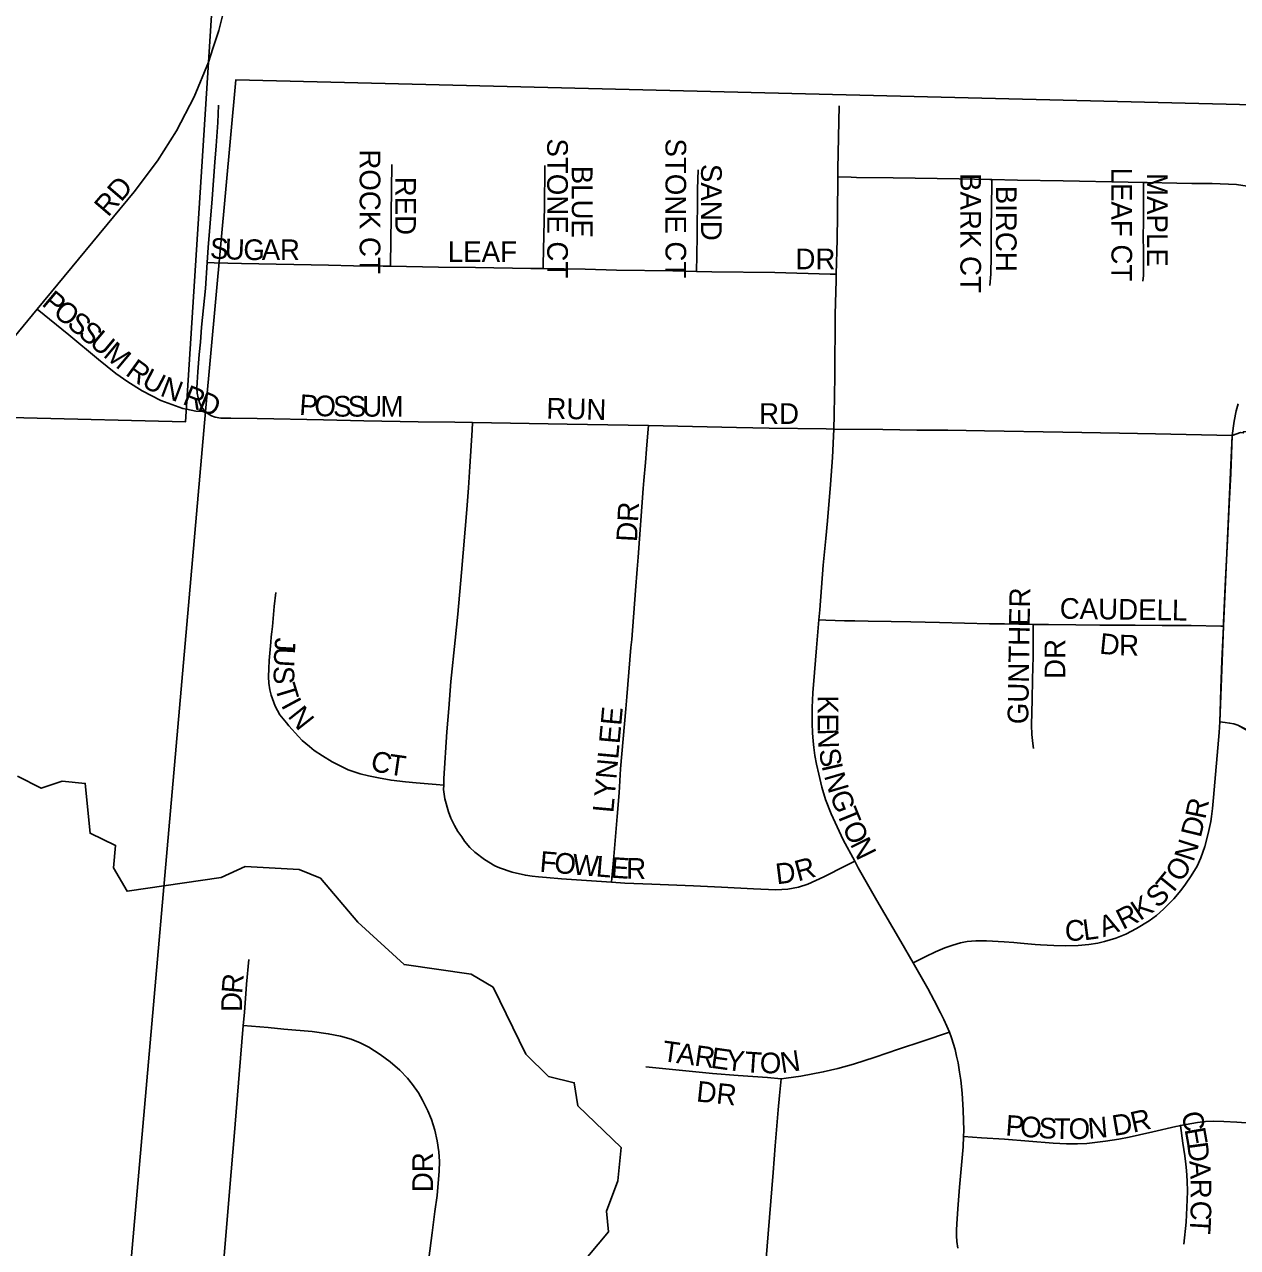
# Model space of a CAD drawing. Extents: x 1410790 to 1770854, y 448063 to 770588.
# Drawn here: x 1517804 to 1520737, y 603957 to 606914 of the extents above; entities that cross this region are included whole.
import ezdxf

# ---------------------------------------------------------------- set-up
doc = ezdxf.new("R2010")
doc.units = 0
for name, color, linetype in [('GM_X_City_Street', 7, 'Continuous'), ('GM_X_City_Street_Text', 7, 'Continuous'), ('GM_X_Corporation', 7, 'Continuous'), ('GM_X_Minor_River', 7, 'Continuous'), ('GM_X_Township_Road', 7, 'Continuous')]:
    doc.layers.add(name, color=color, linetype=linetype)

msp = doc.modelspace()

# ---------------------------------------------------------------- linework, layer by layer
at = {"layer": 'GM_X_City_Street'}
for points in [[(1517616.1, 605962), (1517834.7, 606226.3), (1518069.3, 606510), (1518125.8, 606584.8), (1518171.8, 606657.6), (1518214.2, 606739.2), (1518249, 606822.9), (1518259.8, 606856)], [(1519770.4, 606545.8), (1519770.5, 606565), (1519773.9, 606717.3)], [(1518688.6, 606329.9), (1518688.8, 606341), (1518689.8, 606384), (1518690.8, 606456.1), (1518692.1, 606575.6)], [(1519058.1, 606324.3), (1519058.3, 606334.2), (1519061, 606475.4), (1519062, 606567.3), (1519062.2, 606573.8)], [(1519428.7, 606317.5), (1519429.4, 606355.4), (1519430.3, 606404.3), (1519431.2, 606504.1), (1519431.3, 606516.4), (1519432.5, 606562.7)], [(1519766.4, 606310.4), (1519766.4, 606310.4), (1519768.5, 606394.3), (1519769.6, 606453.4), (1519770.4, 606545.8)], [(1520142.9, 606539.8), (1520137.7, 606539.9), (1520064, 606540.9), (1519903.9, 606543.3), (1519815.7, 606544.5), (1519802.7, 606544.8), (1519770.4, 606545.8)], [(1520138, 606283.5), (1520140.3, 606310.9), (1520141.3, 606355.2), (1520141.3, 606417.4), (1520142.8, 606531), (1520142.9, 606539.8)], [(1520509.3, 606532.5), (1520472.5, 606533.5), (1520315.4, 606536.7), (1520204.3, 606537.8), (1520142.9, 606539.8)], [(1520508, 606293.7), (1520509.3, 606307.1), (1520509.3, 606319.8), (1520509.3, 606342.7), (1520508.9, 606364.3), (1520508.8, 606403.2), (1520509.2, 606435.8), (1520509.3, 606522.1), (1520509.3, 606532.5)], [(1520759.8, 606523.6), (1520733.9, 606527.1), (1520675.2, 606529.5), (1520626.1, 606529.8), (1520590.2, 606530.6), (1520518.3, 606532.3), (1520509.3, 606532.5)], [(1518246, 606338.6), (1518262.8, 606338.1), (1518329.1, 606336.2), (1518538.8, 606332.8), (1518599.6, 606331.1), (1518671.4, 606330.3), (1518688.6, 606329.9)], [(1518688.6, 606329.9), (1518804.8, 606327.4), (1518894.1, 606326.4), (1519028.5, 606324.7), (1519058.1, 606324.3)], [(1519058.1, 606324.3), (1519159.6, 606323), (1519235, 606320.5), (1519371.2, 606318.6), (1519428.7, 606317.5)], [(1519428.7, 606317.5), (1519465.8, 606316.7), (1519618.4, 606314.4), (1519751.5, 606310.8), (1519766.4, 606310.4)], [(1519760.6, 605936.3), (1519761.3, 605970.2), (1519763.3, 606064.1), (1519764.1, 606213.6), (1519766, 606295.7), (1519766.4, 606310.4)], [(1517834.7, 606226.3), (1517911.4, 606164.2), (1517983.4, 606104.5), (1518024.8, 606070.3), (1518053.9, 606050.7), (1518088.8, 606028.2), (1518133.9, 606005.6), (1518187, 605986), (1518195.7, 605984.3)], [(1518241.8, 605978.4), (1518248.2, 605972.7), (1518256.1, 605968.1), (1518265.2, 605964.9), (1518278.8, 605962.8), (1518302.9, 605962.6), (1518366.5, 605961.4), (1518526.7, 605958.4), (1518624.8, 605956.3), (1518755.9, 605953.6), (1518844.3, 605952.7), (1518887.3, 605951.9)], [(1520723.6, 605920.9), (1520728.5, 605955.6), (1520733.3, 605980.2), (1520737.8, 605997.2)], [(1518817.8, 605075.5), (1518818.2, 605090.9), (1518825.1, 605203.8), (1518829.6, 605260.8), (1518835.2, 605326.2), (1518845, 605425.5), (1518851.7, 605488.5), (1518860.4, 605589.5), (1518873.5, 605741.8), (1518877.2, 605793.8), (1518880.6, 605845.4), (1518886.1, 605933.5), (1518887.3, 605951.9)], [(1518887.3, 605951.9), (1519116, 605947.9), (1519263.4, 605945.7), (1519312.7, 605944.7)], [(1519223.1, 604840.5), (1519224, 604850), (1519228.9, 604902.9), (1519232.9, 604951.2), (1519236.9, 604999.2), (1519241.4, 605057), (1519245.3, 605114.3), (1519258, 605260), (1519260.6, 605289), (1519270.3, 605408.1), (1519272, 605427.3), (1519281.4, 605546.1), (1519285.4, 605597.8), (1519287.5, 605626.8), (1519299.9, 605792.5), (1519301.6, 605811.8), (1519305.4, 605855.7), (1519307.7, 605887.2), (1519311.1, 605926.7), (1519312.7, 605944.7)], [(1519312.7, 605944.7), (1519525.5, 605940.3), (1519604.1, 605938.7), (1519741.8, 605936.4), (1519760.6, 605936.3)], [(1519724.4, 605474.7), (1519726.6, 605498.9), (1519735.1, 605606.7), (1519741.3, 605671.8), (1519745.2, 605714.2), (1519752.9, 605802.5), (1519757.8, 605867.2), (1519760.6, 605936.3)], [(1519760.6, 605936.3), (1519879.3, 605935.3), (1519961.2, 605933.8), (1520036.6, 605933.8), (1520124.9, 605932.1), (1520314.3, 605928.5), (1520450.9, 605926.2), (1520538.3, 605924.6), (1520723.6, 605920.9)], [(1520723.6, 605920.9), (1520720, 605829), (1520716.3, 605753.4), (1520712.9, 605683.1), (1520707, 605556.8), (1520702.9, 605468.7), (1520702.5, 605459.6)], [(1518411.6, 605540.7), (1518408, 605506.8), (1518403.5, 605458.8), (1518402.1, 605446.2), (1518400.9, 605433.7), (1518399.6, 605421), (1518395.8, 605376.5), (1518394.5, 605357), (1518393.8, 605337.5), (1518394.7, 605321.5), (1518397.3, 605305.3), (1518400.8, 605292.7), (1518410.4, 605266.4), (1518415.6, 605256.1), (1518421.8, 605245.6), (1518425.3, 605240.6), (1518437.3, 605225.6), (1518443, 605218.5), (1518466.2, 605192.5), (1518475.5, 605183.5), (1518493.5, 605168.3), (1518504.2, 605159.4), (1518524.3, 605146.5), (1518547.8, 605131.8), (1518567.5, 605121.6), (1518586.6, 605112.2), (1518615.6, 605102.4), (1518636, 605097.5), (1518660.1, 605092.6), (1518690.4, 605087.2), (1518725.5, 605082.9), (1518750.7, 605081.1), (1518799.3, 605077), (1518817.8, 605075.5)], [(1519811.1, 604891.1), (1519782.9, 604942.7), (1519754.3, 605005.5), (1519740.7, 605040.7), (1519731.7, 605070.3), (1519724.1, 605102), (1519718.6, 605126.1), (1519714.6, 605147.2), (1519712.1, 605166.3), (1519710.6, 605181.9), (1519709.1, 605202), (1519708.5, 605224.1), (1519708.5, 605263.3), (1519710.1, 605298.5), (1519713.7, 605347.9), (1519718.4, 605407.5), (1519724.4, 605474.7)], [(1519724.4, 605474.7), (1519741.2, 605474.1), (1519786.7, 605472.7), (1519811.3, 605472.7), (1519843.7, 605472), (1519899.4, 605470.5), (1519947.1, 605469.8), (1520015.7, 605468.4), (1520137.1, 605465.5), (1520173.2, 605465.5), (1520242.5, 605464)], [(1520243.3, 605164.2), (1520241.5, 605176.3), (1520239.6, 605197.5), (1520238.3, 605220.2), (1520239.8, 605282.1), (1520241.3, 605330.9), (1520241.9, 605360), (1520242.4, 605385.5), (1520242.5, 605453.2), (1520242.5, 605464)], [(1520242.5, 605464), (1520279.4, 605463.3), (1520345.8, 605462.6), (1520403.6, 605461.8), (1520441.9, 605461.8), (1520489.4, 605461.8), (1520554.6, 605461.1), (1520624.4, 605461.4), (1520696.2, 605459.7), (1520702.5, 605459.6)], [(1520702.5, 605459.6), (1520698.8, 605375.5), (1520695.8, 605309.7), (1520695.1, 605278), (1520694.1, 605228.2)], [(1519952.2, 604645.8), (1519983.3, 604661.1), (1520006.7, 604672.5), (1520029.2, 604681.8), (1520048.2, 604688.5), (1520066.8, 604693.7), (1520082.7, 604696.8), (1520103.9, 604699.1), (1520130, 604698.6), (1520172.8, 604696.5), (1520195.5, 604694.5), (1520211.7, 604693), (1520247.4, 604690.3), (1520260.2, 604689.3), (1520292.6, 604687.3), (1520320.3, 604686.7), (1520351.2, 604687.6), (1520377, 604690.1), (1520399.2, 604693.4), (1520414.7, 604697), (1520442.5, 604705.5), (1520466.4, 604715.1), (1520492.3, 604728.3), (1520522.7, 604746.8), (1520540.8, 604760.2), (1520557.6, 604775.2), (1520582.6, 604800.7), (1520599.3, 604820.3), (1520610.7, 604836), (1520624.5, 604856.3), (1520638.7, 604879.7), (1520648.2, 604899.6), (1520657.5, 604927.1), (1520665.8, 604958.5), (1520671.7, 604987.1), (1520674, 604999.8), (1520676.4, 605019.1), (1520678.8, 605045), (1520692, 605202.7), (1520694.1, 605228.2)], [(1520694.1, 605228.2), (1520706.7, 605226.8), (1520717.5, 605225.2), (1520727.2, 605223.2), (1520737.2, 605220.2), (1520748.9, 605214.2), (1520787.9, 605192.4), (1520833.2, 605170.1), (1520904.5, 605136.4), (1520942.4, 605120.5), (1520954.4, 605115.2)], [(1519223.1, 604840.5), (1519151, 604845.7), (1519102.1, 604848.9), (1519066.4, 604851.8), (1519047.1, 604853.3), (1519031.4, 604854.9), (1519015.2, 604857.2), (1518983.3, 604864.7), (1518952.6, 604875.1), (1518941.3, 604880.3), (1518916.2, 604895.5), (1518892.7, 604913.4), (1518880.8, 604924.6), (1518868.1, 604939.4), (1518861.5, 604950.6), (1518851.6, 604963.5), (1518843.4, 604977.5), (1518834.9, 604995.1), (1518829.2, 605010.4), (1518820.5, 605042), (1518817.5, 605064.7), (1518817.8, 605075.5)], [(1519811.1, 604891.1), (1519788.9, 604879.9), (1519736.2, 604853.2), (1519697.5, 604835.5), (1519675.6, 604828.5), (1519649.8, 604823.9), (1519620.6, 604822.1), (1519566.3, 604824.2), (1519489.3, 604828.6), (1519421.5, 604832), (1519321, 604835.8), (1519255.6, 604838.2), (1519223.1, 604840.5)], [(1519952.2, 604645.8), (1519922.9, 604697.3), (1519864.6, 604796.2), (1519819.6, 604875.5), (1519811.1, 604891.1)], [(1518333.2, 604494.4), (1518335.9, 604525.7), (1518341.2, 604594.4), (1518346.3, 604653.6)], [(1520040, 604478), (1520034, 604492.1), (1520026.7, 604508.9), (1520018.6, 604525.1), (1520003.5, 604554.8), (1519987.7, 604583.2), (1519952.2, 604645.8)], [(1518224.2, 603506.3), (1518226.4, 603510.7), (1518232.7, 603525.6), (1518244.2, 603555.9), (1518252.5, 603583.9), (1518256.4, 603598.5), (1518260.4, 603618.6), (1518262.9, 603635.6), (1518264.9, 603655.7), (1518274.4, 603784.7), (1518286.2, 603928.4), (1518304, 604140.6), (1518311.9, 604235.3), (1518323.3, 604375.6), (1518333.2, 604494.4)], [(1518781.3, 603930.9), (1518789.7, 603992.5), (1518794.6, 604031.4), (1518796.4, 604044.3), (1518801.6, 604083.3), (1518806.3, 604142.2), (1518807.1, 604165.6), (1518805.7, 604188.8), (1518801.9, 604215.2), (1518796, 604241.1), (1518787.9, 604266.5), (1518778.9, 604288.1), (1518766.7, 604313.6), (1518756.7, 604331.6), (1518742.5, 604351.3), (1518729.9, 604366.9), (1518711.3, 604386.2), (1518688.4, 604406), (1518664.3, 604424.2), (1518636.3, 604442.1), (1518615.3, 604452.6), (1518593.5, 604460.9), (1518567.9, 604468.1), (1518538.7, 604474.3), (1518499.6, 604479.5), (1518430.9, 604485.4), (1518392.9, 604488.9), (1518333.2, 604494.4)], [(1519633.2, 604365.5), (1519645.5, 604366.6), (1519680.5, 604371.7), (1519735.1, 604382), (1519770, 604390.5), (1519807.9, 604400.6), (1519860.9, 604417.5), (1519916.8, 604436.6), (1519975.9, 604456.1), (1520040, 604478)], [(1520074.2, 604225.4), (1520074.2, 604225.4), (1520074.7, 604240), (1520073.5, 604289.5), (1520070.8, 604330.2), (1520067.8, 604361.9), (1520064.6, 604381.3), (1520061.3, 604404.1), (1520057.5, 604419.8), (1520053.6, 604435.8), (1520044.7, 604464.2), (1520040, 604478)], [(1519306.4, 604394), (1519467.1, 604378.1), (1519529.2, 604372.9), (1519565.2, 604370.6), (1519600.7, 604368.2), (1519633.2, 604365.5)], [(1519596.6, 603920.8), (1519613.9, 604138.6), (1519618.8, 604203.4), (1519626.1, 604290.6), (1519629.4, 604324.9), (1519633.2, 604365.5)], [(1520598.4, 604252.2), (1520612.3, 604255), (1520639.5, 604259.5), (1520659.4, 604261.7), (1520679.2, 604262.6), (1520703.1, 604262.1), (1520735.1, 604260.2), (1520769, 604258.2), (1520809.4, 604254.7), (1520873.1, 604249.8)], [(1520074.2, 604225.4), (1520117.5, 604222.6), (1520173, 604219), (1520290.6, 604209.7), (1520323.3, 604208.3), (1520349.5, 604208.1), (1520372.3, 604209.2), (1520391.7, 604211), (1520417.4, 604214.2), (1520449.4, 604219.4), (1520474.7, 604224.4), (1520499.9, 604229.8), (1520531.4, 604236.8), (1520587.2, 604249.7), (1520596.5, 604251.8), (1520598.4, 604252.2)], [(1520606.8, 603965.1), (1520612.5, 604018.9), (1520614.3, 604053.8), (1520615.6, 604092.7), (1520614.8, 604118.2), (1520613, 604143.5), (1520611.7, 604158.9), (1520609, 604178.8), (1520604.6, 604209.3), (1520598.4, 604252.2)], [(1520060.2, 603955.9), (1520058.2, 603972), (1520057.3, 603985.6), (1520057.3, 603999.6), (1520057.8, 604014.7), (1520060.4, 604050.5), (1520064.3, 604103.6), (1520073.1, 604200.4), (1520074.2, 604225.4)]]:
    msp.add_lwpolyline(points, dxfattribs=at)
at = {"layer": 'GM_X_Corporation'}
for points in [[(1518270.4, 607164.1), (1518193.2, 605953.5), (1517411.3, 605972.6), (1516491, 605995.1), (1516499.4, 606342.8), (1515317.9, 606371.3), (1515253.9, 605493.3), (1515181.9, 605496), (1515138.6, 605013.3), (1515066.2, 604167.4), (1514899.6, 602242.1)], [(1518023.6, 603486.5), (1518241.8, 605978.4), (1518315.5, 606780.6), (1521298.7, 606707.3), (1521248.2, 605901.1), (1521112.8, 605913.3), (1520758.8, 605930.1), (1520750.6, 605929.5), (1520750.3, 605926.9), (1520743.4, 605927.9), (1520723.6, 605920.9), (1520702.5, 605459.5), (1520694.1, 605228.2), (1520706.7, 605226.8), (1520717.5, 605225.2), (1520727.2, 605223.2), (1520737.2, 605220.2), (1520880.1, 605147.9), (1520954.5, 605115.2), (1520873.1, 604249.8), (1520769.2, 603257.1)]]:
    msp.add_lwpolyline(points, dxfattribs=at)
at = {"layer": 'GM_X_Minor_River'}
msp.add_lwpolyline([(1519120, 603880.8), (1519216.3, 603995), (1519211.3, 604045.3), (1519238.7, 604118.9), (1519246.3, 604198.9), (1519142, 604299.5), (1519133.1, 604355.8), (1519071.3, 604371.2), (1519016.2, 604424.5), (1518937.2, 604586.7), (1518883.7, 604617.9), (1518721.9, 604641.5), (1518609.7, 604744.2), (1518519.6, 604850.4), (1518468, 604871.6), (1518337.9, 604878.5), (1518279.3, 604851.7), (1518052.3, 604818.5), (1518019.4, 604875.4), (1518024.4, 604929.4), (1517962.9, 604958.8), (1517951.2, 605079.4), (1517895.2, 605084.6), (1517844.8, 605067.7), (1517787.3, 605097)], dxfattribs=at)
at = {"layer": 'GM_X_Township_Road'}
for points in [[(1518259.8, 606856), (1518274, 606899.6), (1518292.4, 606975)], [(1518246, 606338.6), (1518248.6, 606375.5), (1518257.5, 606493.1), (1518264.7, 606581.4), (1518267.5, 606620.6), (1518271.5, 606677.6), (1518273.6, 606719.1)], [(1518241.8, 605978.4), (1518241.3, 605979), (1518235.4, 605985.6), (1518231.6, 605990.9), (1518227, 606000.7), (1518223.9, 606011.3), (1518221.8, 606022.8), (1518221.1, 606034.7), (1518221.5, 606048.6), (1518223.4, 606074.6), (1518226.4, 606116.4), (1518229.4, 606146), (1518232.3, 606182.3), (1518241.6, 606276.4), (1518246, 606338.6)], [(1518195.7, 605984.3), (1518218.7, 605979.8), (1518241.8, 605978.4)]]:
    msp.add_lwpolyline(points, dxfattribs=at)

# ---------------------------------------------------------------- texts
at = {"layer": 'GM_X_City_Street_Text'}
for s, rotation, p in [('STONE CT', 270, (1519067.7, 606638.8)), ('STONE CT', 270, (1519353.7, 606638.8)), ('ROCK CT', 270, (1518614.5, 606612.4)), ('SAND', 270, (1519439.7, 606577.2)), ('RD', 49.3961, (1518006.4, 606446.9)), ('RED', 270, (1518700.5, 606546.4)), ('BLUE', 270, (1519127.3, 606572.8)), ('BARK CT', 270, (1520066.5, 606555.2)), ('LEAF CT', 270, (1520431.7, 606568.4)), ('MAPLE', 270, (1520517.7, 606555.2)), ('BIRCH', 270, (1520152.5, 606524.4)), ('S', 356.9111, (1518251.6, 606349)), ('U', 357.3357, (1518287.2, 606347.1)), ('G', 359.5366, (1518333.2, 606345)), ('A', 359.9929, (1518377.7, 606344.6)), ('R', 0, (1518421.7, 606344.6)), ('LEAF', 0, (1518827.5, 606340.2)), ('DR', 0, (1519667.9, 606322.6)), ('P', 320.1752, (1517843.6, 606236.8)), ('O', 320.1692, (1517870.6, 606214.3)), ('S', 320.1499, (1517904.4, 606186.1)), ('S', 320.1765, (1517931.4, 606163.5)), ('U', 320.1692, (1517958.4, 606141)), ('M', 320.1631, (1517992.2, 606112.8)), ('R', 324.0871, (1518045.9, 606068.3)), ('U', 332.2867, (1518084.6, 606040.9)), ('N', 339.2787, (1518129.6, 606017.7)), ('R', 338.176, (1518183.8, 605997.5)), ('D', 337.2692, (1518220.4, 605982.9)), ('P', 356.0078, (1518467.4, 605970.6)), ('O', 357.7185, (1518504.1, 605968.1)), ('S', 359.8823, (1518550.2, 605966.3)), ('S', 359.9956, (1518585.5, 605966.2)), ('U', 0, (1518620.7, 605966.2)), ('M', 0, (1518664.7, 605966.2)), ('RUN', 358.532, (1519065.3, 605961.8)), ('RD', 0, (1519579.9, 605948.6)), ('DR', 86.989, (1519284.7, 605662.5)), ('GUNTHER', 89.1312, (1520230.5, 605222.2)), ('CAUDELL', 359.1168, (1520306.4, 605477.8)), ('J', 266.7644, (1518410.1, 605432.6)), ('DR', 90, (1520320, 605332)), ('D', 354.3079, (1520401.3, 605393.4)), ('R', 359.3621, (1520449.9, 605388.8)), ('U', 266.7615, (1518408.9, 605410.7)), ('S', 270.3911, (1518406.3, 605363.3)), ('T', 286.8593, (1518408.9, 605312.6)), ('I', 298.3109, (1518423.3, 605268.9)), ('N', 308.3544, (1518439, 605241.5)), ('K', 270.1858, (1519721.3, 605292.4)), ('LYNLEE', 84.804, (1519227.5, 605007)), ('E', 270.1838, (1519721.4, 605248.4)), ('N', 272.2474, (1519721.6, 605211.2)), ('C', 346.2435, (1518637.9, 605111.9)), ('T', 351.8213, (1518681.6, 605101.4)), ('S', 280.1533, (1519724.1, 605159.8)), ('I', 282.8239, (1519730.8, 605122.6)), ('N', 286.3337, (1519736.6, 605098)), ('G', 290.4734, (1519750.2, 605052)), ('R', 78.2778, (1520658.5, 604991.1)), ('T', 292.1753, (1519766.2, 605009.2)), ('O', 294.1304, (1519780.2, 604974.9)), ('D', 76.0963, (1520647.4, 604946.4)), ('N', 296.4416, (1519799.1, 604932.8)), ('N', 72.3803, (1520630, 604887.9)), ('F', 355.1581, (1519048.3, 604866.2)), ('O', 355.1839, (1519083.4, 604863.2)), ('W', 355.1686, (1519127.2, 604859.5)), ('L', 355.1581, (1519184.2, 604854.7)), ('E', 356.0959, (1519220.2, 604851.7)), ('R', 359.2813, (1519258.3, 604849.1)), ('D', 7.0559, (1519622.9, 604835.3)), ('R', 15.1982, (1519674, 604842.2)), ('O', 57.6642, (1520600.6, 604838.1)), ('T', 50.9643, (1520574.7, 604805.5)), ('S', 42.9132, (1520543.7, 604776)), ('K', 34.1674, (1520500.7, 604746.1)), ('R', 26.9296, (1520459.5, 604724.7)), ('C', 0.3643, (1520319.2, 604699)), ('L', 7.6238, (1520365.7, 604699.8)), ('A', 19.6278, (1520411.7, 604707.1)), ('R', 84.8935, (1518330.2, 604569.6)), ('D', 89.2568, (1518329.7, 604526.6)), ('T', 352.0244, (1519343.7, 604408.5)), ('A', 352.0379, (1519378.5, 604403.6)), ('R', 352.0363, (1519422.1, 604397.5)), ('E', 352.0244, (1519461.3, 604392.1)), ('Y', 353.2366, (1519497.3, 604387)), ('T', 356.2092, (1519543.8, 604381.6)), ('O', 358.4446, (1519581.1, 604379.2)), ('N', 8.6567, (1519634.8, 604378.6)), ('DR', 353.9946, (1519426.8, 604310.7)), ('R', 12.6582, (1520484.1, 604234.6)), ('P', 355.7888, (1520174.6, 604228.2)), ('O', 355.8099, (1520209.7, 604225.6)), ('S', 356.4251, (1520254.2, 604222.3)), ('T', 359.0348, (1520291.8, 604220.1)), ('O', 0.6291, (1520328.5, 604219.4)), ('N', 5.0179, (1520376.7, 604220.1)), ('D', 9.7739, (1520438.1, 604226.6)), ('C', 280.3646, (1520601.1, 604282.2)), ('E', 280.1045, (1520608.2, 604243.3)), ('D', 277.5968, (1520614.3, 604209.2)), ('DR', 90, (1518791.7, 604091.2)), ('A', 273.729, (1520620.1, 604166.5)), ('R', 270.5343, (1520622.9, 604123.3)), ('C', 269.6114, (1520623.2, 604070.7)), ('T', 266.8565, (1520623, 604031.8))]:
    msp.add_text(s, height=50, rotation=rotation, dxfattribs=at).set_placement(p)

doc.saveas('drawing.dxf')
